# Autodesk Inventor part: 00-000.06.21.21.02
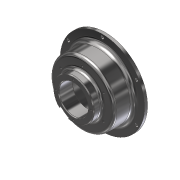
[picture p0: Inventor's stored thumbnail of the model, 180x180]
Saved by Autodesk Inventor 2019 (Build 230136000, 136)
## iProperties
Created: 2019-01
Part Number: 00-000.06.21.21.02
Material: Steel, Mild
Document SubType Name: Modeling
Designer: m.vorobev
Density: 7.85 g/cm^3
Appearance: Semi-Polished
Author: m.vorobev
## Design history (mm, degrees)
sketch "Sketch1"
  geometry: L1 (145, 0)-(100, 0); L2 (100, 0)-(100, 15); L3 (100, 15)-(145, 15); L4 (145, 15)-(145, 0); L5 (100, 15)-(110, 15); L6 (110, 15)-(110, 38.134); L7 (110, 38.134)-(100, 38.134); L8 (100, 38.134)-(100, 15); L9 (110, 38.134)-(100, 38.134); L10 (100, 38.134)-(100, 85); L11 (100, 85)-(110, 85); L12 (110, 85)-(110, 38.134); L13 (100, 85)-(70, 85); L14 (70, 85)-(70, 67); L15 (70, 67)-(100, 67); L16 (100, 67)-(100, 85); L17 (50, 65)-(70, 65); L18 (70, 65)-(70, 115); L19 (70, 115)-(50, 115); L20 (50, 115)-(50, 65); L21 (0, 36.823)-(0, 0); L22 (100, 0)-(125, 0); L23 (100, 4)-(100, 0); L24 (145, 0)-(125, 0); L25 (125, 0)-(125, 5); L26 (125, 5)-(145, 5); L27 (145, 5)-(145, 0); 1 further point
  constraints: 54 end point, 12 parallel, 7 horizontal, 6 perpendicular, 2 collinear, 1 horizontal alignment, 1 midpoint
  dimensions: "d0" = 290 diameter of L4 L21; "d1" = 220 diameter of L12 L21; "d2" = 140 diameter of L18 L21; "d3" = 200 diameter of L10 L21; "d4" = 15 distance of L3.end L1.start; "d7" = 50 distance of L19.end L17.start; "d8" = 100 diameter of L20 L21; "d9" = 115 distance between parallel lines of L1 L19; "d87" = 30 distance between parallel lines of L19 L11; "d88" = 52 distance between parallel lines of L15 L3; "d89" = 5 distance of L24.end L25.end; "d90" = 250 diameter of L25 L21
revolve "Revolution1" sketch "Sketch1" stored, may be unused: angle "d16" = 90 deg
fillet "Fillet1" dims "d17" = 10, "d18" = 15, "d19" = 3
chamfer "Chamfer1" distance "d20" = 3; stored, may be unused: second distance "d21" = 2, angle "d22" = 45 deg
chamfer "Chamfer2" distance "d23" = 2.5; stored, may be unused: second distance "d24" = 2, angle "d25" = 45 deg
sketch "Sketch2"
  geometry: L1 (43.589, 90)-(-43.589, 90); L2 (-43.589, 90)-(-43.589, 101.006); L3 (-43.589, 101.006)-(43.589, 101.006); L4 (43.589, 101.006)-(43.589, 90); A1 r 100 centre (0, 0) between (43.589, 90) and (-43.589, 90) reference; 1 further point
  constraints: 8 end point, 2 parallel, 2 point on circle, 1 centre point, 1 horizontal, 1 perpendicular, 1 other
  dimensions: "d27" = 90 distance from line of point (0, 0) L1
extrude "Extrusion1" join sketch "Sketch2" distance "d28" = 22; taper "d29" = 0 deg
sketch "Sketch3"
  geometry: 6 further points; 1 other entity
  constraints: 2 other
hole "Hole1" sketch "Sketch3" diameter "d30" = 20; stored, may be unused: countersink angle "d34" = 90 deg, drill point angle "d36" = 118 deg; dims "d31" = 6, "d32" = 4, "d33" = 2, "d35" = 25
chamfer "Chamfer3" distance "d37" = 1; stored, may be unused: second distance "d38" = 2, angle "d39" = 45 deg
pattern_circular "Circular Pattern1" dims angle "d41" = 360 deg
sketch "Sketch6"
  geometry: L1 (0, 0)-(0, -60)
  constraints: 2 end point, 1 vertical
  dimensions: "d58" = 60 distance of L1.start L1.end
hole "Hole3" sketch "Sketch6" at (0, -60) diameter "d59" = 6.647; stored, may be unused: countersink angle "d63" = 90 deg, drill point angle "d65" = 118 deg; dims "d60" = 59.25, "d61" = 16, "d62" = 2, "d64" = 100.7
pattern_circular "Circular Pattern3" dims angle "d67" = 360 deg
sketch "Sketch7"
  geometry: L1 (0, 0)-(0, 135)
  constraints: 2 end point, 1 vertical
  dimensions: "d69" = 135 distance of L1.start L1.end
hole "Hole4" sketch "Sketch7" at (0, 135) diameter "d70" = 11; stored, may be unused: countersink angle "d74" = 90 deg, drill point angle "d76" = 118 deg; dims "d71" = 59.25, "d72" = 16, "d73" = 2, "d75" = 100.7
pattern_circular "Circular Pattern4" dims angle "d78" = 360 deg
sketch "Sketch8"
  geometry: L1 (87.178, 0)-(-5.485, 0); L2 (-5.485, 0)-(-5.485, -67.713); L3 (-5.485, -67.713)-(87.178, -67.713); L4 (87.178, -67.713)-(87.178, 0); C1 r 25 at (43.589, -22); 1 further point
  constraints: 8 end point, 2 parallel, 1 centre point, 1 coincident, 1 horizontal, 1 perpendicular
  dimensions: "d80" = 50 diameter of C1
extrude "Extrusion2" cut sketch "Sketch8" stored distance "d81" = 20; taper "d82" = 0 deg; dims "d0" = 290, "d1" = 220, "d2" = 140, "d3" = 200, "d4" = 15, "d7" = 50, "d8" = 100, "d9" = 115, "d87" = 30, "d88" = 52, "d89" = 5, "d90" = 250
pattern_circular "Circular Pattern5" dims angle "d84" = 360 deg
delete_face "Delete Face1"
delete_face "Delete Face2"
delete_face "Delete Face3"
delete_face "Delete Face4"
fillet "Fillet3" dims "d86" = 3
sketch "Sketch9"
  geometry: L1 (-73.171, -90.736)-(-41.994, -108.736); L2 (-41.994, -108.736)-(-13.412, -59.229); L3 (-13.412, -59.229)-(-44.588, -41.229); L4 (-44.588, -41.229)-(-73.171, -90.736); L5 (0, 0)-(-50.677, 0); L6 (-50.677, 0)-(-50.677, 24.836); L7 (-50.677, 24.836)-(0, 24.836); L8 (0, 24.836)-(0, 0); L9 (0, 0)-(-29, -50.229); C1 r 70 at (0, 0) reference
  constraints: 18 end point, 4 parallel, 3 perpendicular, 1 horizontal, 1 midpoint
  dimensions: "d91" = 60 deg angle of L5 L9; "d92" = 128 dimension on C1 L3; "d96" = 36 distance of L2.end L3.end
extrude "Extrusion3" cut sketch "Sketch9" distance "d93" = 28; taper "d94" = 0 deg
fillet "Fillet4" dims "d95" = 0.8
sketch "Sketch10"
  geometry: L1 (0, 0)-(0, 85)
  constraints: 2 end point, 1 vertical
  dimensions: "d97" = 85 distance of L1.start L1.end
hole "Hole5" sketch "Sketch10" at (0, 85) diameter "d98" = 8.376; stored, may be unused: countersink angle "d102" = 90 deg, drill point angle "d104" = 118 deg; dims "d99" = 20, "d100" = 4, "d101" = 2, "d103" = 27.3
pattern_circular "Circular Pattern6" dims angle "d106" = 360 deg
body "Solid1"
